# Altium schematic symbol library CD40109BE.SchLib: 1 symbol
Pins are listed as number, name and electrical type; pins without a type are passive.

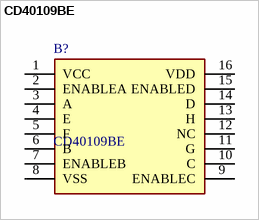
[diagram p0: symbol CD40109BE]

## CD40109BE
designator B?
CD40109BE, Voltage Level Shifter 3-State 3  18 V 16-Pin PDIP; Manufacturer_Name: Texas Instruments; Geometry.Height: 5.08mm
footprint DIP794W53P254L1930H508Q16N
pins: 1 VCC (power), 2 ENABLEA, 3 A, 4 E, 5 F, 6 B, 7 ENABLEB, 8 VSS (power), 9 ENABLEC, 10 C, 11 G, 12 NC, 13 H, 14 D, 15 ENABLED, 16 VDD (power)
